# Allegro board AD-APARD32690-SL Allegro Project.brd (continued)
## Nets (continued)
GND: C2.1 C3.1 C5.2(N2) C7.1 C8.1 C10.1 C11.1 C12.1 C13.2(N2) C14.1 C15.1 C16.1 C17.1 C18.2(N2) C19.1 C20.2(N2) C21.2(N2) C22.2(N2) C23.1 C24.2(N2) C25.2(N2) C26.2(N2) C27.2(N2) C28.2(N2) C29.1 C30.1 C31.2(N2) C32.2(N2) C33.2(N2) C34.1 C35.2(N2) C36.2(N2) C37.1 C38.1 C39.2(N2) C40.2(N2) C41.1 C42.2(N2) C43.1 C44.2(N2) C45.2(N2) C46.2(N2) C47.2(N2) C48.1 C49.2(N2) C50.2(N2) C51.2(N2) C52.2(N2) C53.2(N2) C54.2(N2) C55.1 C56.2(N2) C57.1 C58.2(N2) C59.2(N2) C60.2(N2) C61.2(N2) C62.2(N2) C63.2(N2) C64.1 C65.1 C66.2(N2) C67.2(N2) C68.2(N2) C69.2(N2) C70.2(N2) C71.2(N2) C72.1 C73.2(N2) C74.2(N2) C75.2(N2) C76.2(N2) C77.1 C78.1 C79.2(N2) C80.2(N2) C81.2(N2) C82.2(N2) C83.2(N2) C84.2(N2) C85.2(N2) C86.2(N2) C87.2(N2) C88.2(N2) C89.2(N2) C90.2(N2) C91.2(N2) C92.1 C93.1 C94.2(N2) C95.1 C96.2(N2) C98.2(N2) C100.2(N2) C103.1 C107.1 C108.2(N2) C109.1 C110.1 C111.2(N2) C112.2(N2) C113.1 C114.2(N2) C115.1 C116.2(N2) C117.1 C118.2(N2) C119.2(N2) C120.2(N2) C121.1 C122.2(N2) C123.1 C124.1 C125.1 C126.1 C127.2(N2) C128.1 C129.2(N2) C130.2(N2) C131.1 D1.A(P) D2.2(N2) D6.A(P) D7.A(P) D9.2(N2) D10.A(P) D11.A(P) DS1.C JP1.3 M1.6 M1.12 M1.14 M1.26 M1.30 M1.37 M1.38 M1.39 M1.40 M1.41 M1.42 M1.43 M1.44 M1.45 M1.46 M1.47 M1.48 P2.6 P2.7 P5.4 P8.5 P8.11 P9.3 P9.5 P9.9 P10.A1 P10.A12 P10.B1 P10.B12 P13.5 P13.11 P14.1 P24.1(N1) P25.1(N1) P26.1(N1) P27.1(N1) P28.1(N1) P29.1(N1) P30.1(N1) P31.1(N1) Q1.2(S) Q2.2(S) Q3.2(S) R2.1 R4.2(N2) R6.1 R8.1 R9.1 R10.1 R12.1 R115.2(N2) R117.2(N2) R119.2(N2) R121.2(N2) R123.2(N2) R137.1 R145.2(N2) R147.1 R157.1 R158.1 R165.2(N2) R171.1 R175.1 S1.2(B) S3.2 S3.4(N4) U1.A8 U1.C11 U1.F1 U1.G11 U1.H11 U1.L11 U1.M8 U1.M11 U2.PAD U3.12 U3.20 U3.21 U4.PAD U5.4 U6.B3 U6.C1 U6.E5(VSSQ_2) U7.B3 U7.C1 U7.E5(VSSQ_2) U8.6 U8.PAD U9.9 U9.PAD U10.3 U10.4 U10.5 U10.8 Y1.2 Y1.4 Y2.2 Y2.4
GND_EARTH: C103.2(N2) C104.2(N2) C105.2(N2) C106.2(N2) P1.1 R147.2(N2)
GND_ISO: P11.1 P11.2
VDD_1P1_D: C25.1 C34.2(N2) C36.1 E3.2(N2) R124.1 U1.H12
VDD_3P3_D: C19.2(N2) C20.1 C21.1 C26.1 C27.1 C42.1 C66.1 C67.1 C69.1 C70.1 C71.1 C74.1 C75.1 C86.1 C89.1 C92.2(N2) C115.2(N2) C116.1 C117.2(N2) C118.1 C121.2(N2) C122.1 D5.1 D5.3 DS2.A(P) DS3.A(P) DS4.A(P) E1.2(N2) E5.1 E6.1 JP2.3 JP3.3 JP4.3 M1.9(VCC_IO) M1.10 P2.4 Q4.2(S) R120.1 R125.2(N2) R126.2(N2) R128.1 R132.1 R133.1 R136.1 R141.1 R142.1 R168.2(N2) S2.3 S2.4(N4) S4.1B(N6) S4.2B S4.3B U1.A4 U1.B11 U1.D1 U1.D12 U1.F11 U1.M3 U2.35 U8.12
VDD_5P0: C14.2(N2) C110.2(N2) C112.1 C126.2(N2) C127.1 JP3.1 JP4.1 P2.5 R13.2(N2) R14.2(N2) R15.2(N2) R16.2(N2) R17.1 R170.1 R173.2(N2) U3.4 U3.5 U3.6 U3.16(VIN234) U4.9 U4.10 U4.15 U4.16 U9.1 U9.2 U9.3 U9.4
VDD_5P0_INT: C1.2(N2) C8.2(N2) C11.2(N2) C13.1 JP1.1 L2.2(N2) R1.2(N2) U4.1 U4.2 U4.3
VDDA_BB: C29.2(N2) C31.1 U1.L10
VDDA_RF: C30.2(N2) C33.1 U1.M10
32KIN: C45.1 U1.K10 Y3.1
32KOUT: C53.1 U1.K11 Y3.2(N2)
ADC_IN0: P3.1 R89.2(N2)
ADC_IN1: P3.2 R110.2(N2)
ADC_IN2: P3.3 R90.2(N2)
ADC_IN3: P3.4 R111.2(N2)
ADC_IN4: P3.5 R91.2(N2)
ADC_IN5: P3.6 R112.2(N2)
ADC_IN6: P3.7 R92.2(N2)
ADC_IN7: P3.8(N8) R113.2(N2)
ADIN1100_TS_TIMER_MS_SEL: JP5.1 JP6.1
ADIN1110_INT: R56.1 R168.1 U2.25
ADIN1110_LINK_ST: R22.1 U2.4
ADIN1110_RESET: R55.1 U2.5
ADIN1110_SPI_CFG1: R166.1 U2.37
ADIN1110_TS_CAPT: R49.1 U2.40
ADIN1110_TS_TIMER_MS_SEL: R29.1 U2.30
BLE_LDO_1V1: C37.2(N2) C38.2(N2) C39.1 E4.2(N2) JP11.3
BLE_LDO_IN: C48.2(N2) C51.1 C129.1 JP11.2(COM) U1.K12
BOOT_LOAD_PDN_O: P39.1(N1) U1.J9
BT_ANT: C41.2(N2) L5.1 U1.L12
CAN0B_RX: P7.5 R84.2(N2)
CAN0B_TX: P7.6 R105.2(N2)
CAN1B_RX: P7.7 R85.2(N2)
CAN1B_TX: P7.8(N8) R106.2(N2)
FB1: C1.1 R1.1 R2.2(N2) R123.1 U3.7
FB2: C4.1 R5.1 R6.2(N2) U3.8
FB3: C6.1 R7.1 R8.2(N2) U3.9
FB4: C9.1 R11.1 R12.2(N2) U3.10
GPIO1_NINA: M1.1 P32.1(N1)
GPIO2_NINA: M1.2 P33.1(N1)
GPIO3_NINA: M1.3 P34.1(N1)
GPIO4_NINA: M1.4 P35.1(N1)
GPIO5_NINA: M1.5 P36.1(N1)
GPIO6_NINA: M1.7 P40.1(N1)
GPIO7_NINA: M1.8 P41.1(N1)
GPIO16_NINA: M1.16 P42.1(N1)
GPIO17_NINA: M1.17 P43.1(N1)
GPIO18_NINA: M1.18 P44.1(N1)
GPIO24_NINA: M1.24 P45.2(N2)
GPIO25_NINA: M1.25 P46.2(N2)
GPIO27_NINA: M1.27 P47.1(N1)
GPIO28_NINA: M1.28 P48.1(N1)
GPIO29_NINA: M1.29 P49.1(N1)
GPIO31_NINA: M1.31 P19.2(N2)
GPIO32_NINA: M1.32 P20.2(N2)
GPIO34_NINA: M1.34 P52.1(N1)
GPIO35_NINA: M1.35 P21.2(N2)
GPIO36_NINA: M1.36 P22.2(N2)
GPIO_1: P4.8(N8) R97.2(N2)
GPIO_2: P7.1 R77.2(N2)
GPIO_3: P7.2 R98.2(N2)
GPIO_4: P7.3 R78.2(N2)
GPIO_5: P7.4 R99.2(N2)
GPIO_6: P2.3 R83.2(N2)
GPIO_7: P8.7 R104.2(N2)
GPIO_8: P23.2(N2) R93.2(N2)
GPIO_9: P38.1(N1) R94.2(N2)
GPIO_10: C77.2(N2) R54.1 R133.2(N2) S3.1
GPIO_11: C78.2(N2) R31.1 R136.2(N2) S3.3
GPIO_I2C_1: P13.1 R160.1
GPIO_I2C_2: P13.2 R163.1
GPIO_I2C_3: P13.7 R161.1
GPIO_I2C_4: P13.8 R164.1
GPIO_USR_BTN: C57.2(N2) R71.1 R119.1 S2.1 S2.2
GPIO_USR_LED1: Q1.1 R74.2(N2) R115.1
GPIO_USR_LED2: Q2.1 R53.1 R117.1
GPIO_USR_LED3: Q3.1 R30.1 R121.1
HFXIN: C44.1 U1.L9 Y2.1
HFXOUT: C52.1 U1.M9 Y2.3(N2)
HYP_CLK_N: U1.A9 U6.B1 U7.B1
HYP_CLK_P: U1.A10 U6.B2 U7.B2
HYP_CS0_N: R38.1 U6.A3
HYP_CS1_N: R47.1 R176.1 U7.A3
HYP_D0: U1.C7 U6.D3 U7.D3
HYP_D1: U1.C8 U6.D2 U7.D2
HYP_D2: U1.C9 U6.C4 U7.C4
HYP_D3: U1.C10 U6.D4 U7.D4
HYP_D4: U1.B7 U6.D5 U7.D5
HYP_D5: U1.B8 U6.E3 U7.E3
HYP_D6: U1.B9 U6.E2 U7.E2
HYP_D7: U1.B10 U6.E1 U7.E1
HYP_RSTN: R18.1 U6.A4 U7.A4
HYP_RWDS: R65.1 U6.C3 U7.C3
I2C0A_SCL: P13.3 P13.9 R32.1 R142.2(N2)
I2C0A_SDA: P13.4 P13.10 R57.1 R141.2(N2)
I2C1A_SCL: P5.1 R103.2(N2) R144.1
I2C1A_SDA: P5.2 R82.2(N2) R143.1
IO_REF_ARD: C107.2(N2) C108.1 JP2.2(COM) P2.2 R143.2(N2) R144.2(N2)
LT8692S_1P1: C7.2(N2) C9.2(N2) C17.2(N2) C100.1 E3.1 L1.2(N2) R11.2(N2)
LT8692S_1P8: C6.2(N2) C10.2(N2) C16.2(N2) C98.1 E2.1 L4.2(N2) R7.2(N2)
LT8692S_3P3: C4.2(N2) C12.2(N2) C95.2(N2) C96.1 E1.1 L3.2(N2) R5.2(N2)
LT8692S_PG: DS1.A(P) R17.2(N2) U3.19
MCU_RESET_N: C55.2(N2) P9.10(N5) R120.2(N2) S1.1 U1.K9
OWM_IO: P6.4 P18.1 R21.1 R126.1
OWM_PE: P6.3 Q4.1 R48.1 R132.2(N2)
PI+: C106.1 D8.1 P1.3(N3) P16.1 P16.2(N2) R155.2(N2)
PI-: C104.1 D8.2(N2) P1.2 P17.1 P17.2(N2) R156.2(N2)
QSPI_SCK: U1.J1 U5.6
QSPI_SDIO0: U1.J2 U5.5
QSPI_SDIO1: U1.H2 U5.2
QSPI_SDIO2: U1.J3 U5.3(WP_N/SIO2)
QSPI_SDIO3: U1.H3 U5.7
QSPI_SS0: U1.H1 U5.1
RESET_NINA: M1.19 R114.2(N2)
RXN: R135.1 R146.1 U2.13
RXP: R129.1 R140.1 U2.14
SHIELD: C123.2(N2) P10.GND1 P10.GND2 P10.GND3(N9) P10.GND4 R145.1
SPI0_MISO: P4.3 P22.1 R107.2(N2)
SPI0_MOSI: P4.4 P21.1 R87.2(N2)
SPI0_SCK: P4.2 P19.1 R108.2(N2)
SPI0_SDIO2: P4.6 P46.1 R88.2(N2)
SPI0_SDIO3: P4.7 P45.1 R109.2(N2)
SPI0_SS1: P4.1 R86.2(N2)
SPI1A_MISO: P5.6 R45.1
SPI1A_MOSI: P5.7 R72.1
SPI1A_SCLK: P5.5 R44.1
SPI1A_SDIO2: P5.9(N9) R46.1
SPI1A_SDIO3: P5.10 R73.1
SPI1A_SS0: P5.8 R69.1
SPI1A_SS1: P6.1 R70.1
SPI1A_SS2: P6.2 R43.1
SPI2_MISO_MAXQ1065: R75.2(N2) U8.4
SPI2_MOSI_MAXQ1065: R96.2(N2) U8.3
SPI2_SCK_MAXQ1065: R95.2(N2) U8.2
SPI2A_SS0_MAXQ1065: R76.2(N2) U8.5
SPI3A_MISO_ADIN1110: R167.1 U1.C3 U2.2
SPI3A_MOSI_ADIN1110: U1.B2 U2.1
SPI3A_SCLK_ADIN1110: U1.B3 U2.38
SPI3A_SS0_ADIN1110: R24.1 U2.29
SPI4A_MISO: JP8.3 R59.1
SPI4A_MOSI: JP7.3 R33.1
SPI4A_SCLK: JP10.3 R34.1
SPI4A_SDIO2: JP6.3 R60.1
SPI4A_SDIO3: P8.10 R35.1
SPI4A_SS0: JP9.3 R58.1
SPI4A_SS1: JP5.3 R61.1
SWPD_EN: R138.1 U2.33
TCK: P9.4 R159.1
TDO: P4.5 P20.1 R20.1
TMS: P9.2 R162.1
TRX_N: C99.1 D9.1 P15.1(N1) R134.2(N2) R146.2(N2) R151.1 T1.2
TRX_P: C97.2(N2) D2.1 P12.1(N1) R131.2(N2) R140.2(N2) R148.1 T1.1
TXN: R129.2(N2) R134.1 U2.12
TXP: R131.1 R135.2(N2) U2.15
UART0_RX: P9.8 R79.2(N2)
UART0_TX: P9.6 R100.2(N2)
UART1A_CTS: JP10.1 P6.6 R80.2(N2)
UART1A_RTS: JP9.1 P6.5 R81.2(N2)
UART1A_RX: JP8.1 P6.7 R101.2(N2)
UART1A_TX: JP7.1 P6.8(N8) R102.2(N2)
UART2A_CTS: M1.20 R36.1
UART2A_RTS: M1.21 R62.1
UART2A_RX: M1.22 R37.1
UART2A_TX: M1.23 R63.1
UNNAMED_2_ADLT3040_I358_FAULTN: R170.2(N2) U9.5
UNNAMED_2_ADLT3040_I358_FS: C124.2(N2) R169.1 R174.2(N2) R175.2(N2) U9.7
UNNAMED_2_ADLT3040_I358_ILIM: R171.2(N2) U9.6
UNNAMED_2_ADLT3040_I358_OUT1: C128.2(N2) JP11.1 U9.10 U9.11 U9.12
UNNAMED_2_ADLT3040_I358_VIN: C125.2(N2) R169.2(N2) U9.8(VIN)
UNNAMED_2_ADLT8692S_I193_EN: C2.2(N2) C3.2(N2) C15.2(N2) D1.C D4.C F3.2(N2) R3.2(N2) U3.1 U3.2
UNNAMED_2_ADLT8692S_I193_EN1: R3.1 R4.1 U3.3
UNNAMED_2_ADLT8692S_I193_INTVCC: C5.1 U3.11
UNNAMED_2_ADLT8692S_I193_SW1: L2.1 U3.17
UNNAMED_2_ADLT8692S_I193_SW2: L3.1 U3.15
UNNAMED_2_ADLT8692S_I193_SW3: L4.1 U3.14
UNNAMED_2_ADLT8692S_I193_SW4: L1.1 U3.13
UNNAMED_2_CAP_I379_N1: C130.1 D11.C R172.1 R173.1 U10.1 U10.2
UNNAMED_2_CAP_I385_N2: C131.2(N2) P37.1 R174.1 U10.6(VOUT_S) U10.7
UNNAMED_2_DIO_I282_N: D3.C D4.A(P)
UNNAMED_2_FERRITE_I316_N1: E4.1 R124.2(N2)
UNNAMED_2_LINLTC4415_I130_CLIM1: R9.2(N2) U4.4
UNNAMED_2_LINLTC4415_I130_CLIM2: R10.2(N2) U4.5
UNNAMED_2_LINLTC4415_I130_EN2N: JP1.2(COM) U4.6
UNNAMED_2_LINLTC4415_I130_STAT1N: R15.1 U4.14
UNNAMED_2_LINLTC4415_I130_STAT2N: R16.1 U4.11
UNNAMED_2_LINLTC4415_I130_WARN1N: R14.1 U4.13
UNNAMED_2_LINLTC4415_I130_WARN2N: R13.1 U4.12(WARN2_N)
UNNAMED_2_NC2P_I395_N2: P37.2(N2) R172.2(N2)
UNNAMED_3_ADMAX32690_I367_P0_6: R48.2(N2) U1.G2
UNNAMED_3_ADMAX32690_I367_P0_7: R53.2(N2) U1.F2
UNNAMED_3_ADMAX32690_I367_P0_9: R21.2(N2) U1.G1
UNNAMED_3_ADMAX32690_I367_P0_10: R30.2(N2) U1.F3
UNNAMED_3_ADMAX32690_I367_P0_11: R31.2(N2) U1.C1
UNNAMED_3_ADMAX32690_I367_P0_13: R24.2(N2) U1.A3
UNNAMED_3_ADMAX32690_I367_P0_14: R18.2(N2) U1.C6
UNNAMED_3_ADMAX32690_I367_P0_16: R56.2(N2) U1.D3
UNNAMED_3_ADMAX32690_I367_P0_17: R55.2(N2) U1.C2
UNNAMED_3_ADMAX32690_I367_P0_18: R57.2(N2) U1.G6
UNNAMED_3_ADMAX32690_I367_P0_19: R54.2(N2) U1.D2
UNNAMED_3_ADMAX32690_I367_P0_20: R32.2(N2) U1.F6
UNNAMED_3_ADMAX32690_I367_P0_21: R22.2(N2) U1.F4
UNNAMED_3_ADMAX32690_I367_P0_22: R29.2(N2) U1.F7
UNNAMED_3_ADMAX32690_I367_P0_23: R49.2(N2) U1.G7
UNNAMED_3_ADMAX32690_I367_P0_24: R159.2(N2) U1.H8
UNNAMED_3_ADMAX32690_I367_P0_25: R162.2(N2) U1.J8
UNNAMED_3_ADMAX32690_I367_P0_26: R160.2(N2) U1.G4
UNNAMED_3_ADMAX32690_I367_P0_27: R163.2(N2) U1.H4
UNNAMED_3_ADMAX32690_I367_P0_28: R161.2(N2) U1.F5
UNNAMED_3_ADMAX32690_I367_P0_29: R164.2(N2) U1.G5
UNNAMED_3_ADMAX32690_I367_P0_30: R20.2(N2) U1.K1
UNNAMED_3_ADMAX32690_I367_P1: R58.2(N2) U1.E5
UNNAMED_3_ADMAX32690_I367_P1_1: R59.2(N2) U1.D5
UNNAMED_3_ADMAX32690_I367_P1_2: R60.2(N2) U1.B4
UNNAMED_3_ADMAX32690_I367_P1_3: R63.2(N2) U1.E4
UNNAMED_3_ADMAX32690_I367_P1_4: R61.2(N2) U1.B5
UNNAMED_3_ADMAX32690_I367_P1_5: R62.2(N2) U1.A2
UNNAMED_3_ADMAX32690_I367_P1_7: R65.2(N2) U1.A11
UNNAMED_3_ADMAX32690_I367_P1_9: R34.2(N2) U1.C5
UNNAMED_3_ADMAX32690_I367_P1_10: R33.2(N2) U1.C4
UNNAMED_3_ADMAX32690_I367_P1_11: R35.2(N2) U1.A5
UNNAMED_3_ADMAX32690_I367_P1_12: R36.2(N2) U1.D4
UNNAMED_3_ADMAX32690_I367_P1_15: R38.2(N2) U1.B6
UNNAMED_3_ADMAX32690_I367_P1_16: R37.2(N2) U1.B1
UNNAMED_3_ADMAX32690_I367_P1_19: R69.2(N2) U1.K8
UNNAMED_3_ADMAX32690_I367_P1_20: R71.2(N2) U1.K7
UNNAMED_3_ADMAX32690_I367_P1_21: R70.2(N2) U1.H7
UNNAMED_3_ADMAX32690_I367_P1_22: R72.2(N2) U1.M7
UNNAMED_3_ADMAX32690_I367_P1_23: R73.2(N2) U1.F8
UNNAMED_3_ADMAX32690_I367_P1_24: R44.2(N2) U1.L8
UNNAMED_3_ADMAX32690_I367_P1_25: R43.2(N2) U1.J7
UNNAMED_3_ADMAX32690_I367_P1_28: R45.2(N2) U1.L7
UNNAMED_3_ADMAX32690_I367_P1_29: R46.2(N2) U1.G8
UNNAMED_3_ADMAX32690_I367_P1_30: R47.2(N2) U1.A7
UNNAMED_3_ADMAX32690_I367_P2: R101.1 U1.D6
UNNAMED_3_ADMAX32690_I367_P2_1: R81.1 U1.D7
UNNAMED_3_ADMAX32690_I367_P2_2: R104.1 U1.D9
UNNAMED_3_ADMAX32690_I367_P2_3: R82.1 U1.E2
UNNAMED_3_ADMAX32690_I367_P2_4: R103.1 U1.E3
UNNAMED_3_ADMAX32690_I367_P2_5: R80.1 U1.E6
UNNAMED_3_ADMAX32690_I367_P2_6: R102.1 U1.E7
UNNAMED_3_ADMAX32690_I367_P2_7: R83.1 U1.E9
UNNAMED_3_ADMAX32690_I367_P2_8: R105.1 U1.F9
UNNAMED_3_ADMAX32690_I367_P2_9: R106.1 U1.G3
UNNAMED_3_ADMAX32690_I367_P2_10: R84.1 U1.G9
UNNAMED_3_ADMAX32690_I367_P2_11: R77.1 U1.H5
UNNAMED_3_ADMAX32690_I367_P2_12: R74.1 U1.H6
UNNAMED_3_ADMAX32690_I367_P2_13: R98.1 U1.J4
UNNAMED_3_ADMAX32690_I367_P2_14: R79.1 U1.K5
UNNAMED_3_ADMAX32690_I367_P2_15: R76.1 U1.J6
UNNAMED_3_ADMAX32690_I367_P2_16: R109.1 U1.K2
UNNAMED_3_ADMAX32690_I367_P2_17: R108.1 U1.K3
UNNAMED_3_ADMAX32690_I367_P2_18: R97.1 U1.K4
UNNAMED_3_ADMAX32690_I367_P2_19: R100.1 U1.J5
UNNAMED_3_ADMAX32690_I367_P2_20: R96.1 U1.K6
UNNAMED_3_ADMAX32690_I367_P2_21: R87.1 U1.L1
UNNAMED_3_ADMAX32690_I367_P2_22: R107.1 U1.L2
UNNAMED_3_ADMAX32690_I367_P2_23: R88.1 U1.L3
UNNAMED_3_ADMAX32690_I367_P2_24: R85.1 U1.L4
UNNAMED_3_ADMAX32690_I367_P2_25: R99.1 U1.L5
UNNAMED_3_ADMAX32690_I367_P2_26: R75.1 U1.L6
UNNAMED_3_ADMAX32690_I367_P2_27: R86.1 U1.M2
UNNAMED_3_ADMAX32690_I367_P2_28: R78.1 U1.M5
UNNAMED_3_ADMAX32690_I367_P2_29: R95.1 U1.M6
UNNAMED_3_ADMAX32690_I367_P3: R114.1 U1.D8
UNNAMED_3_ADMAX32690_I367_P3_1: R93.1 U1.E8
UNNAMED_3_ADMAX32690_I367_P3_2: R89.1 U1.E10
UNNAMED_3_ADMAX32690_I367_P3_3: R110.1 U1.E11
UNNAMED_3_ADMAX32690_I367_P3_4: R90.1 U1.E12
UNNAMED_3_ADMAX32690_I367_P3_5: R111.1 U1.F10
UNNAMED_3_ADMAX32690_I367_P3_6: R92.1 U1.F12
UNNAMED_3_ADMAX32690_I367_P3_7: R91.1 U1.G10
UNNAMED_3_ADMAX32690_I367_P3_8: R112.1 U1.H10
UNNAMED_3_ADMAX32690_I367_P3_9: R113.1 U1.J10
UNNAMED_3_ADMAX32690_I367_P4: R94.1 U1.H9
UNNAMED_3_ADMAX32690_I367_VREG1: C18.1 U1.J12
UNNAMED_3_ANT4PV3_I701_FEED: ANT1.4 C43.2(N2) L5.2(N2)
UNNAMED_3_DIOLED4PV5_I542_C1: D5.2 R122.2(N2)
UNNAMED_3_DIOLED4PV5_I542_C2: D5.4(C2) R118.2(N2)
UNNAMED_3_DIOLED_I538_N: DS2.C R116.2(N2)
UNNAMED_3_NC2P_I646_N2: P18.2(N2) R127.2(N2)
UNNAMED_3_RES_I645_N1: Q4.3 R127.1
UNNAMED_3_RES_I698_N1: Q1.3 R116.1
UNNAMED_3_RES_I699_N1: Q2.3 R118.1
UNNAMED_3_RES_I700_N1: Q3.3 R122.1
UNNAMED_7_ADIN1110V2_I781_AVDDH1: C64.2(N2) C90.1 E6.2(N2) U2.16 U2.17
UNNAMED_7_ADIN1110V2_I781_AVDDL: C65.2(N2) C88.1 E5.2(N2) U2.22
UNNAMED_7_ADIN1110V2_I781_CEXT2: C72.2(N2) U2.19
UNNAMED_7_ADIN1110V2_I781_CEXT3: C73.1 U2.20
UNNAMED_7_ADIN1110V2_I781_DLDO1P1: C68.1 C93.2(N2) U2.23 U2.24
UNNAMED_7_ADIN1110V2_I781_LED0: R139.2(N2) U2.3
UNNAMED_7_ADIN1110V2_I781_LED1: R128.2(N2) R130.2(N2) U2.6
UNNAMED_7_ADIN1110V2_I781_TEST1: R125.1 U2.26
UNNAMED_7_ADIN1110V2_I781_TX2P4ENN: R137.2(N2) U2.31
UNNAMED_7_CAP_I819_N1: C102.1 R150.1 R151.2(N2) T1.7(SEC_2)
UNNAMED_7_CAP_I819_N2: C102.2(N2) L6.3 P54.1(N1) R150.2(N2) R154.1
UNNAMED_7_CAP_I823_N1: C101.1 R148.2(N2) R149.1 T1.6
UNNAMED_7_CAP_I823_N2: C101.2(N2) L6.4(N4) P53.1(N1) R149.2(N2) R153.1
UNNAMED_7_CAP_I855_N1: C105.1 R152.2(N2)
UNNAMED_7_CAP_I861_N1: C94.1 C97.1 C99.2(N2) T1.5
UNNAMED_7_CHOKE4PV5_I912_N1: L6.1 R153.2(N2) R155.1
UNNAMED_7_CHOKE4PV5_I912_N2: L6.2 R154.2(N2) R156.1
UNNAMED_7_DIOLED_I752_N: DS3.C R139.1
UNNAMED_7_DIOLED_I761_N: DS4.C R130.1
UNNAMED_7_RES_I857_N1: R152.1 T1.3 T1.4
UNNAMED_7_RES_I906_N2: R166.2(N2) S4.3A
UNNAMED_7_RES_I907_N2: R167.2(N2) S4.2A
UNNAMED_7_RES_I909_N2: R138.2(N2) S4.1A
UNNAMED_9_ADMAXQ1065_I325_CEXT: C91.1 U8.1
UNNAMED_9_ADMAXQ1065_I325_PDWN: P23.1 R165.1 U8.7
UNNAMED_9_CAP_I264_N1: C109.2(N2) C111.1 JP3.2(COM) P13.6 P13.12(VCC2)
UNNAMED_9_CAP_I265_N1: C113.2(N2) C114.1 JP4.2(COM) P8.6 P8.12(VCC2)
UNNAMED_9_CN12PV3_I138_P1: JP9.2(COM) P8.1
UNNAMED_9_CN12PV3_I138_P2: JP7.2(COM) P8.2
UNNAMED_9_CN12PV3_I138_P3: JP8.2(COM) P8.3
UNNAMED_9_CN12PV3_I138_P4: JP10.2(COM) P8.4
UNNAMED_9_CN12PV3_I138_P8: JP5.2(COM) P8.8
UNNAMED_9_CN12PV3_I138_P9: JP6.2(COM) P8.9
UNNAMED_9_CN16PAB4GND_I308_N3: P10.B5 R158.2(N2)
UNNAMED_9_CN16PAB4GND_I314_N3: P10.A5 R157.2(N2)
USB_DN: L7.1 U1.C12
USB_DN_CM: D6.C L7.2 P10.A7 P10.B7
USB_DP: L7.4(N4) U1.B12
USB_DP_CM: D7.C L7.3 P10.A6 P10.B6
VPWR_IN: F3.1 P2.8(N8) P14.2(N2)
VPWR_USB: C120.1 D3.A(P) D10.C P10.A4 P10.A9 P10.B4 P10.B9 U4.7 U4.8
VREF_ADC: C22.1 P5.3 U1.G12
VUSB0P9: C35.1 U1.D11(VUSB0P9)
XTAL_I: C62.1 U2.8 Y1.1
XTAL_O: C63.1 U2.9(XTAL_O) Y1.3(N2)

Pads without a net: ANT1 1 2 3; M1 11 13 15 33; P2 1; P9 7; P10 A8 B8; P11 3; U2 7 10 11 18 21 27 28 32 34 36 39; U3 18; U6 A2 A5 B5 C2 C5; U7 A2 A5 B5 C2 C5; U8 8 9 10 11

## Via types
v1: diameter 0.356, hole 0.203, TOP to BOTTOM, 477 vias
v2: diameter 0.203, hole 0.102, TOP to L2_GND, 547 vias
v3: diameter 0.203, hole 0.102, L2_GND to L3_SIG, 88 vias
v4: diameter 0.203, hole 0.102, L3_SIG to L4_GND, 33 vias
v5: diameter 0.203, hole 0.102, L4_GND to L5_PWR, 12 vias
v6: diameter 0.508, hole 0.254, TOP to BOTTOM, 551 vias

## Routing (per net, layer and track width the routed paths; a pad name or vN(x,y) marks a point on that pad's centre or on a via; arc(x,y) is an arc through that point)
1V8_D: length 100.9
  TOP w0.127: U1.A6 98.73,28.4 98.23,27.91 ; 100.95,25.04 U1.E1
  TOP w0.152: U1.M4 103.87,27.7 104.33,27.24 104.33,26.73 105.03,26.04 v1(105.28,26.04)
  TOP w0.254: 101.12,24.86 100.95,25.04
  TOP w0.305: v1(81.51,27.48) 81.51,28.08 C85.1 81.63,29.08 81.34,29.37 C87.1 81.22,29.37 81.17,29.41 C59.1 ; v1(78.77,32.67) 78.77,33.24 79.06,33.53 C81.1
  TOP w0.381: v1(77.76,27.48) 77.07,27.48 C84.1 77,27.5 C54.1 ; 98.23,27.91 97.53,27.21 C58.1 ; v1(77.77,36.43) 77.75,36.45 77.12,36.45 C82.1 77,36.52 C49.1 ; 81.52,37.35 v1(81.52,36.43) ; 81.52,37.35 C80.1 C79.1 ; 81.52,37.35 81.51,37.35 C46.1 ; v1(78.76,23.72) 78.76,23 C83.1 ; v1(101.09,22.67) 101.09,23.26 C28.1 101.12,23.29 C56.1 101.12,24.86 ; R176.2 v1(84.71,22.99)
  TOP w0.508: C58.1 96.03,27.21 C23.2 v1(95.44,27.19) 95.42,27.21 C32.1 ; v6(127,24.38) C119.1 124.49,25.05 P9.1 ; JP2.1 v6(42.53,7) ; C40.1 101.2,13.52 C76.1 99.92,13.49 U5.8
  L2_GND w0.127: 102.23,31.43 102.23,30.54 102.35,30.43 v2(102.35,30.15)
  L2_GND w0.152: v1(102.74,31.94) 102.23,31.43
  L3_SIG w0.089: v1(98.01,31.78) 99,31.78 100.6,30.18 v3(100.6,29.8)
  L6_PWR w0.508: v1(95.44,27.19) 95.44,27.88
  L6_PWR w0.889: v6(40.58,8.38) v6(41.27,8.38) v6(41.97,8.38) 42.53,7.82 v6(42.53,7) 42.53,5.6 43.43,4.7 69.6,4.7 73.85,8.95 73.85,20.83 75.5,22.48
  BOTTOM w0.127: U6.E4 v1(77.77,36.43) ; U7.B4 v1(81.51,27.48) ; U7.D1 v1(78.76,23.72) ; U6.D1 v1(78.77,32.67) ; U6.B4 v1(81.52,36.43) ; U7.E4 v1(77.76,27.48)
  BOTTOM w0.381: v1(105.28,26.04) 105.79,26.55 C61.1 C47.1 ; v1(102.74,31.94) 103.22,31.94 C60.1 ; v1(98.01,31.78) 98.33,31.46 C50.1
  BOTTOM w0.508: C24.1 103.47,30.56 C60.1
  vias: v6(100.58,12.79) v6(101.22,12.79)
GND: length 964.4
  TOP w0.127: v2(101.59,25.52) 101.3,25.81 U1.F1 ; v2(105,29.53) 103.95,29.53 103.52,29.1 U1.M8 ; U1.A8 v2(98.49,29.1)
  TOP w0.152: U1.L11 U1.M11 arc(103.98,30.27) 104.47,30.59
  TOP w0.254: U3.20 28.71,15.1 v6(29.08,14.73) ; U8.6 v1(105.56,17.46) ; v6(29.84,12.95) 29.98,13.09 U3.12
  TOP w0.381: C123.1 11.1,32.14 ; C123.1 11.65,31.56 ; C123.1 11.1,30.98 ; C112.2 54.64,5.78 ; C112.2 54.64,4.76 ; C112.2 55.18,5.27 ; 90.83,9.12 U5.4 ; U5.4 90.83,10.24 ; U5.4 91.88,9.68 ; U5.4 v1(89.53,9.68) ; R158.1 3.82,20.94 ; R158.1 3.82,19.7 ; R158.1 3.25,20.32 ; 125.17,7.53 Q1.2 ; Q1.2 125.93,8.48 ; Q1.2 125.17,9.77 v1(124.78,10.16) ; Q1.2 124.41,8.48 ; C109.1 142.44,39.62 ; C109.1 141.27,39.62 ; C109.1 v6(141.86,40.26) ; 118.44,9.54 R117.2 ; R117.2 117.86,10.16 ; R117.2 118.18,10.41 v1(117.79,10.41) ; P8.5 146.48,4.57 ; P8.5 144.09,4.57 ; P8.5 145.29,3.38 ; 147.83,39.95 P13.11 ; P13.11 147.83,42.34 ; P13.11 146.63,41.15 ; P13.11 149.02,41.15 ; 66.99,7.98 D11.A ; D11.A 67.86,8.69 ; D11.A 66.99,9.4 ; D11.A 66.13,8.69 ; C129.2 56.32,22.7 ; C129.2 55.31,22.7 ; C129.2 55.82,23.24 ; C110.1 55.21,6.54 ; C110.1 54.67,7.12 ; C110.1 54.67,5.96 ; 11.1,27.89 R157.1 11.1,29.13 ; v6(58.48,18.73) 58.32,18.57 C125.1 58.32,17.88 58.49,17.71 U9.9 58.49,14.74 U9.PAD ; 3.44,6.1 P14.1 ; P14.1 4.83,4.71 ; P14.1 4.83,7.48 ; P14.1 6.21,6.1 ; C128.1 55.63,18.68 ; C128.1 55.63,17.51 ; C128.1 55.09,18.1 ; P30.1 136.55,1.91 ; P30.1 134.09,1.91 ; P30.1 135.32,3.14 ; v1(110.74,32.35) C55.1 ; P28.1 13.53,32.79 ; P28.1 14.76,31.56 ; P28.1 12.29,31.56 ; P28.1 13.53,30.33 ; S3.2 131.32,2.75 ; S3.2 v1(131.32,0.76) ; S3.2 131.95,1.88 ; 143.7,17.82 P29.1 ; P29.1 142.47,19.05 ; P29.1 144.93,19.05 ; v6(149.73,18.41) C117.1 v6(149.03,17.72) ; 64.86,12.05 U10.5 ; U10.5 65.29,12.97 ; U10.5 64.86,13.88 ; 62.91,12.05 U10.8 ; U10.8 62.91,13.88 ; U10.8 62.47,12.97 ; 29.06,50.8 P31.1 ; P31.1 30.29,49.57 ; P31.1 30.29,52.03 ; P31.1 31.52,50.8 ; v6(145.87,17.72) C115.1 v6(145.1,18.41) ; 61.85,44.99 C42.2 ; C42.2 62.36,44.45 ; C42.2 62.87,44.99 ; 41.91,49.54 P5.4 ; P5.4 43.17,50.8 ; P5.4 41.91,52.06 ; P5.4 40.65,50.8 ; v6(142.11,3.68) C113.1 ; C113.1 141.53,2.98 ; C113.1 142.7,2.98 ; D10.A 13.13,25.08 ; D10.A 12.47,25.64 ; D10.A 12.47,24.52 ; D10.A 11.81,25.08 ; 122.81,30.1 P9.9 124.46,30.72 ; S1.2 115.21,34.02 ; S1.2 114.11,33.37 ; S1.2 113,34.02 ; S1.2 114.11,34.66 ; 135.42,42.42 P25.1 ; P25.1 136.65,41.19 ; P25.1 136.65,43.65 ; P25.1 137.88,42.42 ; 47.05,5.96 C107.1 47.05,7.12 ; 51,18.61 JP1.3 51.56,19.62 ; C118.2 v6(149.73,19.56) ; C118.2 149.03,19.58 C89.2 ; C118.2 149.01,19.05 ; C118.2 149.01,20.07 ; 61.33,17.51 C124.1 ; C124.1 61.88,18.1 ; C124.1 61.33,18.68 ; Q3.2 122.12,8.48 ; Q3.2 121.36,7.53 ; Q3.2 121.36,9.77 v1(120.97,10.16) ; Q3.2 120.6,8.48 ; C76.2 99.95,15.01 ; C76.2 100.46,14.47 ; C76.2 99.44,14.47 ; v1(99.31,35.56) v1(99.31,35.05) 99.31,34.55 C27.2 99.31,34.54 99.31,33.43 C70.2 ; D2.2 53.88,39.84 ; D2.2 53.37,39.15 ; D2.2 53.37,40.61 v1(53.34,40.64) ; D2.2 52.86,39.84 ; P13.5 146.48,41.15 ; P13.5 144.09,41.15 ; P13.5 145.29,39.95 ; P13.5 145.29,42.34 ; C114.2 143.83,2.96 ; C114.2 142.81,2.96 ; C114.2 v6(143.32,3.68) ; v1(79.76,23.72) 79.76,22.95 C83.2 ; 132.92,10.6 C77.1 132.33,11.14 ; R115.2 v1(125.41,10.16) ; U10.4 65.29,8.37 ; U10.4 64.86,7.45 ; U10.4 64.86,9.28 ; 65.75,14.61 C131.1 65.21,14.02 ; P2.6 57.07,1.6 ; P2.6 57.07,3.48 ; P2.6 55.19,3.48 ; P2.6 55.19,1.6 ; 147.93,34.29 P27.1 ; P27.1 150.39,34.29 ; P27.1 149.16,33.06 ; P27.1 149.16,35.52 ; R121.2 v1(121.6,10.16) ; 55.59,10.22 C127.2 ; C127.2 55.06,10.73 ; C127.2 55.59,11.24 ; C116.2 145.87,19.58 C86.2 ; C116.2 145.89,20.07 ; C116.2 145.89,19.05 ; C116.2 v6(145.1,19.56) ; 122.81,27.56 P9.5 124.46,26.94 ; 12.7,0.89 P26.1 ; P26.1 12.7,4.06 ; P26.1 14.29,2.48 ; P26.1 11.11,2.48 ; 26.9,1.27 DS1.C ; DS1.C 26.9,2.54 ; DS1.C 27.55,1.91 ; DS1.C 26.26,1.91 ; v1(77.76,28.48) 77.03,28.48 C84.2 75.9,28.48 C54.2 ; 63.63,39.75 R137.1 64.21,40.37 ; v1(53.34,32.13) 53.37,32.16 D9.2 ; v1(75.88,38.04) C49.2 76.03,37.37 76.96,37.37 77.03,37.44 C82.2 77.1,37.43 v1(77.77,37.43) ; 57.73,1.6 P2.7 ; P2.7 59.61,1.6 ; P2.7 57.73,3.48 ; P2.7 59.61,3.48 ; 2.1,15.85 P24.1 ; P24.1 2.1,18.31 ; P24.1 0.86,17.08 ; P24.1 3.33,17.08 ; P8.11 149.02,4.57 ; P8.11 147.83,3.38 ; P8.11 147.83,5.77 ; P8.11 146.63,4.57 ; v1(116.2,18.67) C57.1 ; C130.2 65.02,6.6 ; C130.2 64.49,6.1 ; C130.2 64.49,7.11 ; 60.63,9.91 R171.1 60.01,9.34 ; Q2.2 118.31,8.48 ; Q2.2 116.79,8.48 ; Q2.2 117.55,7.53 ; Q2.2 117.55,9.77 117.28,10.03 v1(117.28,10.41) ; 124.46,26.91 P9.3 122.81,26.29 ; C83.2 80.32,22.92 ; C83.2 79.79,23.43 ; C83.2 79.79,22.42 ; D9.2 53.37,33.63 ; D9.2 53.88,32.93 ; D9.2 52.86,32.93 ; C111.2 143.57,39.6 ; C111.2 142.56,39.6 ; C111.2 v6(143.07,40.26) ; 116.28,17.59 R119.2 116.85,16.97 ; 55.02,9.53 C126.1 ; C126.1 55.57,10.11 ; C126.1 55.57,8.94 ; 27.24,6.16 C100.2 27.78,5.65 ; S3.4 v1(130.05,0.76) ; S3.4 130.05,2.75 ; S3.4 129.41,1.88 ; 128.45,10.6 C78.1 129.03,11.14 ; R165.2 104.95,14.53 ; R165.2 103.71,14.53 ; R165.2 104.33,15.11 ; v1(104.9,32.83) C51.2 ; C108.2 47.02,5.78 ; C108.2 47.56,5.27 ; C108.2 47.02,4.76 ; 26.15,12.18 R2.1 24.9,12.18 ; 24.75,12.18 R123.2 23.51,12.18 ; 64.21,7.45 U10.3 64.21,9.28 ; C48.1 v1(104.9,33.97) ; v6(101.22,15.17) C40.2 ; C5.2 31.76,9.15 ; C5.2 30.59,9.15 ; C5.2 v6(31.18,7.94) ; C119.2 127,26.54 ; C119.2 126.49,26.01 ; C119.2 127.51,26.01 ; 58.75,20.45 R175.1 59.32,21.07
  TOP w0.508: P9.5 v6(126.3,27.56) ; v6(24.13,7.18) R8.1 ; v6(26.54,5.59) C16.1 ; R157.1 v6(11.81,28.51) ; 96.36,32.62 C21.2 ; 96.36,32.62 C67.2 ; 96.36,32.62 v6(96.36,33.3) ; P10.B12 P10.A1 ; P9.3 v6(126.3,26.29) ; C17.1 27.76,6.18 C100.2 27.75,6.13 v6(27.75,5.59) ; v6(27.75,7.94) 27.75,8.58 R12.1 ; C92.1 64.08,38.8 v6(63.44,38.8) ; v6(60.64,36.89) C90.2 ; v6(20.57,5.59) C95.1 ; R9.1 v1(48.01,20.7) ; v6(25.46,5.59) C98.2 ; R10.1 v1(46.86,20.7) ; v6(24.13,12.83) R123.2 ; v6(21.65,5.59) C96.2 ; JP1.3 v1(51,20.7) ; P10.B1 P10.A12 ; C107.1 v6(47.62,6.54) ; v6(25.53,12.83) R2.1 ; v6(60.64,37.91) C64.1 ; v6(22.73,7.94) R6.1 ; C69.2 64.21,37.28 63.82,36.89 v6(63.44,36.89) ; P9.9 v6(126.3,30.1)
  TOP w0.635: R145.2 v6(4.83,33.66)
  L2_GND w0.127: 100.08,30.69 100.08,30.42 100.25,30.24 v2(100.25,30.15)
  L2_GND w0.381: P27.1 149.16,35.52 ; P27.1 149.16,33.06 ; P27.1 147.93,34.29 ; P27.1 150.39,34.29 ; 144.09,4.57 P8.5 ; P8.5 145.29,3.38 ; P8.5 145.29,5.77 ; P8.5 146.48,4.57 ; P25.1 137.88,42.42 ; P25.1 136.65,43.65 ; P25.1 136.65,41.19 ; P25.1 135.42,42.42 ; P30.1 135.32,3.14 ; P30.1 136.55,1.91 ; P30.1 134.09,1.91 ; 0.86,17.08 P24.1 ; P24.1 2.1,18.31 ; P24.1 2.1,15.85 ; P24.1 3.33,17.08 ; P14.1 6.21,6.1 ; P14.1 4.83,7.48 ; P14.1 4.83,4.71 ; P14.1 3.44,6.1 ; 143.7,17.82 P29.1 ; P29.1 142.47,19.05 ; P29.1 144.93,19.05 ; P29.1 143.7,20.28 ; 146.63,41.15 P13.11 ; P13.11 149.02,41.15 ; P13.11 147.83,39.95 ; P13.11 147.83,42.34 ; 55.19,1.6 P2.6 ; P2.6 57.07,1.6 ; P2.6 55.19,3.48 ; P2.6 57.07,3.48 ; 57.73,1.6 P2.7 ; P2.7 59.61,1.6 ; P2.7 57.73,3.48 ; P2.7 59.61,3.48 ; P31.1 30.29,52.03 ; P31.1 29.06,50.8 ; P31.1 31.52,50.8 ; P31.1 30.29,49.57 ; P13.5 145.29,42.34 ; P13.5 144.09,41.15 ; P13.5 146.48,41.15 ; P13.5 145.29,39.95 ; P8.11 147.83,5.77 ; P8.11 149.02,4.57 ; P8.11 146.63,4.57 ; P8.11 147.83,3.38 ; P5.4 41.91,52.06 ; P5.4 43.17,50.8 ; P5.4 40.65,50.8 ; P5.4 41.91,49.54 ; 12.29,31.56 P28.1 ; P28.1 14.76,31.56 ; P28.1 13.53,30.33 ; P28.1 13.53,32.79 ; 11.11,2.48 P26.1 ; P26.1 14.29,2.48 ; P26.1 12.7,4.06 ; P26.1 12.7,0.89
  L3_SIG w0.381: P14.1 6.21,6.1 ; P14.1 4.83,4.71 ; P14.1 3.44,6.1 ; P14.1 4.83,7.48 ; P8.5 146.48,4.57 ; P8.5 144.09,4.57 ; P8.5 145.29,3.38 ; P8.5 145.29,5.77 ; 12.7,0.89 P26.1 ; P26.1 14.29,2.48 ; P26.1 11.11,2.48 ; P26.1 12.7,4.06 ; 13.53,30.33 P28.1 ; P28.1 13.53,32.79 ; P28.1 12.29,31.56 ; P28.1 14.76,31.56 ; 41.91,49.54 P5.4 ; P5.4 43.17,50.8 ; P5.4 41.91,52.06 ; P5.4 40.65,50.8 ; 2.1,15.85 P24.1 ; P24.1 0.86,17.08 ; P24.1 2.1,18.31 ; P24.1 3.33,17.08 ; 143.7,17.82 P29.1 ; P29.1 143.7,20.28 ; P29.1 144.93,19.05 ; P29.1 142.47,19.05 ; 29.06,50.8 P31.1 ; P31.1 30.29,52.03 ; P31.1 31.52,50.8 ; P31.1 30.29,49.57 ; P2.7 59.61,3.48 ; P2.7 57.73,1.6 ; P2.7 59.61,1.6 ; P2.7 57.73,3.48 ; 147.83,39.95 P13.11 ; P13.11 146.63,41.15 ; P13.11 149.02,41.15 ; P13.11 147.83,42.34 ; P27.1 150.39,34.29 ; P27.1 147.93,34.29 ; P27.1 149.16,35.52 ; P27.1 149.16,33.06 ; P2.6 57.07,1.6 ; P2.6 55.19,1.6 ; P2.6 57.07,3.48 ; P2.6 55.19,3.48 ; P25.1 137.88,42.42 ; P25.1 135.42,42.42 ; P25.1 136.65,41.19 ; P25.1 136.65,43.65 ; 146.63,4.57 P8.11 ; P8.11 147.83,5.77 ; P8.11 149.02,4.57 ; P8.11 147.83,3.38 ; P13.5 145.29,42.34 ; P13.5 144.09,41.15 ; P13.5 146.48,41.15 ; P13.5 145.29,39.95 ; P30.1 136.55,1.91 ; P30.1 135.32,3.14 ; P30.1 134.09,1.91
  L4_GND w0.381: P5.4 43.17,50.8 ; P5.4 40.65,50.8 ; P5.4 41.91,52.06 ; P5.4 41.91,49.54 ; P30.1 136.55,1.91 ; P30.1 134.09,1.91 ; P30.1 135.32,3.14 ; P13.5 145.29,42.34 ; P13.5 146.48,41.15 ; P13.5 144.09,41.15 ; P13.5 145.29,39.95 ; 57.73,3.48 P2.7 ; P2.7 59.61,1.6 ; P2.7 59.61,3.48 ; P2.7 57.73,1.6 ; P2.6 57.07,1.6 ; P2.6 57.07,3.48 ; P2.6 55.19,1.6 ; P2.6 55.19,3.48 ; 136.65,41.19 P25.1 ; P25.1 136.65,43.65 ; P25.1 137.88,42.42 ; P25.1 135.42,42.42 ; 11.11,2.48 P26.1 ; P26.1 14.29,2.48 ; P26.1 12.7,0.89 ; P26.1 12.7,4.06 ; P13.11 149.02,41.15 ; P13.11 146.63,41.15 ; P13.11 147.83,39.95 ; P13.11 147.83,42.34 ; 147.83,3.38 P8.11 ; P8.11 146.63,4.57 ; P8.11 147.83,5.77 ; P8.11 149.02,4.57 ; 149.16,33.06 P27.1 ; P27.1 147.93,34.29 ; P27.1 149.16,35.52 ; P27.1 150.39,34.29 ; 3.44,6.1 P14.1 ; P14.1 4.83,4.71 ; P14.1 6.21,6.1 ; P14.1 4.83,7.48 ; 30.29,49.57 P31.1 ; P31.1 30.29,52.03 ; P31.1 29.06,50.8 ; P31.1 31.52,50.8 ; 0.86,17.08 P24.1 ; P24.1 2.1,18.31 ; P24.1 2.1,15.85 ; P24.1 3.33,17.08 ; P8.5 146.48,4.57 ; P8.5 145.29,5.77 ; P8.5 144.09,4.57 ; P8.5 145.29,3.38 ; 13.53,30.33 P28.1 ; P28.1 12.29,31.56 ; P28.1 13.53,32.79 ; P28.1 14.76,31.56 ; 143.7,17.82 P29.1 ; P29.1 142.47,19.05 ; P29.1 144.93,19.05 ; P29.1 143.7,20.28
  L5_PWR w0.381: 146.63,4.57 P8.11 ; P8.11 149.02,4.57 ; P8.11 147.83,5.77 ; P8.11 147.83,3.38 ; P28.1 13.53,32.79 ; P28.1 13.53,30.33 ; P28.1 12.29,31.56 ; P28.1 14.76,31.56 ; P30.1 136.55,1.91 ; P30.1 134.09,1.91 ; P30.1 135.32,3.14 ; P25.1 137.88,42.42 ; P25.1 136.65,41.19 ; P25.1 136.65,43.65 ; P25.1 135.42,42.42 ; P26.1 14.29,2.48 ; P26.1 12.7,0.89 ; P26.1 11.11,2.48 ; P26.1 12.7,4.06 ; 142.47,19.05 P29.1 ; P29.1 143.7,17.82 ; P29.1 143.7,20.28 ; P29.1 144.93,19.05 ; P27.1 150.39,34.29 ; P27.1 147.93,34.29 ; P27.1 149.16,35.52 ; P27.1 149.16,33.06 ; P14.1 4.83,7.48 ; P14.1 4.83,4.71 ; P14.1 6.21,6.1 ; P14.1 3.44,6.1 ; 145.29,39.95 P13.5 ; P13.5 145.29,42.34 ; P13.5 144.09,41.15 ; P13.5 146.48,41.15 ; P31.1 30.29,52.03 ; P31.1 29.06,50.8 ; P31.1 31.52,50.8 ; P31.1 30.29,49.57 ; P2.7 59.61,1.6 ; P2.7 59.61,3.48 ; P2.7 57.73,1.6 ; P2.7 57.73,3.48 ; 55.19,3.48 P2.6 ; P2.6 57.07,3.48 ; P2.6 55.19,1.6 ; P2.6 57.07,1.6 ; P13.11 149.02,41.15 ; P13.11 147.83,42.34 ; P13.11 146.63,41.15 ; P13.11 147.83,39.95 ; P24.1 2.1,18.31 ; P24.1 0.86,17.08 ; P24.1 3.33,17.08 ; P24.1 2.1,15.85 ; P5.4 43.17,50.8 ; P5.4 40.65,50.8 ; P5.4 41.91,52.06 ; 145.29,3.38 P8.5 ; P8.5 144.09,4.57 ; P8.5 145.29,5.77 ; P8.5 146.48,4.57
  L7_GND w0.381: 11.11,2.48 P26.1 ; P26.1 12.7,4.06 ; P26.1 12.7,0.89 ; P26.1 14.29,2.48 ; P8.11 147.83,5.77 ; P8.11 147.83,3.38 ; P8.11 146.63,4.57 ; P8.11 149.02,4.57 ; P30.1 135.32,3.14 ; P30.1 134.09,1.91 ; P30.1 136.55,1.91 ; P13.11 147.83,42.34 ; P13.11 146.63,41.15 ; P13.11 147.83,39.95 ; P13.11 149.02,41.15 ; P27.1 149.16,35.52 ; P27.1 150.39,34.29 ; P27.1 147.93,34.29 ; P27.1 149.16,33.06 ; 144.09,41.15 P13.5 ; P13.5 145.29,42.34 ; P13.5 145.29,39.95 ; P13.5 146.48,41.15 ; 13.53,30.33 P28.1 ; P28.1 14.76,31.56 ; P28.1 13.53,32.79 ; P28.1 12.29,31.56 ; P2.7 59.61,3.48 ; P2.7 57.73,3.48 ; P2.7 59.61,1.6 ; P2.7 57.73,1.6 ; P5.4 43.17,50.8 ; P5.4 41.91,49.54 ; P5.4 40.65,50.8 ; P5.4 41.91,52.06 ; P29.1 144.93,19.05 ; P29.1 142.47,19.05 ; P29.1 143.7,17.82 ; P29.1 143.7,20.28 ; P31.1 31.52,50.8 ; P31.1 30.29,49.57 ; P31.1 30.29,52.03 ; P31.1 29.06,50.8 ; 4.83,4.71 P14.1 ; P14.1 6.21,6.1 ; P14.1 4.83,7.48 ; P14.1 3.44,6.1 ; P8.5 146.48,4.57 ; P8.5 145.29,5.77 ; P8.5 145.29,3.38 ; P8.5 144.09,4.57 ; P25.1 136.65,43.65 ; P25.1 135.42,42.42 ; P25.1 136.65,41.19 ; P25.1 137.88,42.42 ; 55.19,3.48 P2.6 ; P2.6 55.19,1.6 ; P2.6 57.07,1.6 ; P2.6 57.07,3.48 ; P24.1 3.33,17.08 ; P24.1 2.1,18.31 ; P24.1 0.86,17.08 ; P24.1 2.1,15.85
  L8_SIG w0.381: 147.83,39.95 P13.11 ; P13.11 146.63,41.15 ; P13.11 149.02,41.15 ; P13.11 147.83,42.34 ; P8.11 149.02,4.57 ; P8.11 146.63,4.57 ; P8.11 147.83,5.77 ; P8.11 147.83,3.38 ; P29.1 143.7,20.28 ; P29.1 144.93,19.05 ; P29.1 143.7,17.82 ; P29.1 142.47,19.05 ; P26.1 12.7,4.06 ; P26.1 12.7,0.89 ; P26.1 14.29,2.48 ; P26.1 11.11,2.48 ; 57.73,3.48 P2.7 ; P2.7 57.73,1.6 ; P2.7 59.61,3.48 ; P2.7 59.61,1.6 ; 55.19,1.6 P2.6 ; P2.6 57.07,3.48 ; P2.6 55.19,3.48 ; P2.6 57.07,1.6 ; P27.1 150.39,34.29 ; P27.1 147.93,34.29 ; P27.1 149.16,33.06 ; P27.1 149.16,35.52 ; 2.1,15.85 P24.1 ; P24.1 0.86,17.08 ; P24.1 3.33,17.08 ; P24.1 2.1,18.31 ; P30.1 135.32,3.14 ; P30.1 134.09,1.91 ; P30.1 136.55,1.91 ; 29.06,50.8 P31.1 ; P31.1 30.29,52.03 ; P31.1 30.29,49.57 ; P31.1 31.52,50.8 ; 3.44,6.1 P14.1 ; P14.1 4.83,4.71 ; P14.1 4.83,7.48 ; P14.1 6.21,6.1 ; P5.4 41.91,52.06 ; P5.4 43.17,50.8 ; P5.4 41.91,49.54 ; P5.4 40.65,50.8 ; 144.09,41.15 P13.5 ; P13.5 145.29,42.34 ; P13.5 146.48,41.15 ; P13.5 145.29,39.95 ; P28.1 14.76,31.56 ; P28.1 12.29,31.56 ; P28.1 13.53,32.79 ; P28.1 13.53,30.33 ; 136.65,41.19 P25.1 ; P25.1 135.42,42.42 ; P25.1 136.65,43.65 ; P25.1 137.88,42.42 ; P8.5 146.48,4.57 ; P8.5 144.09,4.57 ; P8.5 145.29,5.77 ; P8.5 145.29,3.38
  L9_GND w0.381: 136.65,41.19 P25.1 ; P25.1 137.88,42.42 ; P25.1 135.42,42.42 ; P25.1 136.65,43.65 ; P28.1 13.53,32.79 ; P28.1 12.29,31.56 ; P28.1 14.76,31.56 ; P28.1 13.53,30.33 ; 57.73,1.6 P2.7 ; P2.7 57.73,3.48 ; P2.7 59.61,3.48 ; P2.7 59.61,1.6 ; P14.1 6.21,6.1 ; P14.1 4.83,7.48 ; P14.1 3.44,6.1 ; P14.1 4.83,4.71 ; 143.7,17.82 P29.1 ; P29.1 142.47,19.05 ; P29.1 144.93,19.05 ; P29.1 143.7,20.28 ; 145.29,3.38 P8.5 ; P8.5 145.29,5.77 ; P8.5 146.48,4.57 ; P8.5 144.09,4.57 ; P26.1 14.29,2.48 ; P26.1 11.11,2.48 ; P26.1 12.7,0.89 ; P26.1 12.7,4.06 ; P24.1 2.1,18.31 ; P24.1 3.33,17.08 ; P24.1 2.1,15.85 ; P24.1 0.86,17.08 ; P30.1 136.55,1.91 ; P30.1 134.09,1.91 ; P30.1 135.32,3.14 ; P8.11 147.83,5.77 ; P8.11 149.02,4.57 ; P8.11 146.63,4.57 ; P8.11 147.83,3.38 ; 147.83,39.95 P13.11 ; P13.11 146.63,41.15 ; P13.11 147.83,42.34 ; P13.11 149.02,41.15 ; 55.19,1.6 P2.6 ; P2.6 57.07,3.48 ; P2.6 55.19,3.48 ; P2.6 57.07,1.6 ; P13.5 145.29,42.34 ; P13.5 146.48,41.15 ; P13.5 144.09,41.15 ; P13.5 145.29,39.95 ; P5.4 43.17,50.8 ; P5.4 41.91,52.06 ; P5.4 40.65,50.8 ; P5.4 41.91,49.54 ; P27.1 150.39,34.29 ; P27.1 149.16,35.52 ; P27.1 149.16,33.06 ; P27.1 147.93,34.29 ; P31.1 31.52,50.8 ; P31.1 29.06,50.8 ; P31.1 30.29,52.03 ; P31.1 30.29,49.57
  BOTTOM w0.127: U7.E5 v1(77.76,28.48) ; U7.C1 v1(79.76,23.72) ; U7.B3 v1(80.76,25.72) ; U6.E5 v1(77.77,37.43)
  BOTTOM w0.254: v1(8.76,27.88) 9.05,28.16 D7.A ; D6.A 9.05,26.32 v1(8.76,26.61)
  BOTTOM w0.381: 12.29,31.56 P28.1 ; P28.1 13.53,32.79 ; P28.1 14.76,31.56 ; P28.1 13.53,30.33 ; v1(59.5,29.34) 59.5,29.33 Y1.2 ; C34.1 29.53,6.7 ; C34.1 28.94,6.15 ; C34.1 30.11,6.15 ; 147.83,3.38 P8.11 ; P8.11 147.83,5.77 ; P8.11 149.02,4.57 ; P8.11 146.63,4.57 ; 77.73,28.1 U7.E5 ; U7.E5 78.14,28.51 ; U7.E5 78.54,28.1 ; 36.36,5.91 C39.2 ; C39.2 36.36,6.92 ; C39.2 36.89,6.41 ; U7.B3 81.14,26.51 ; U7.B3 81.14,25.69 ; U7.B3 81.54,26.1 ; P2.6 57.07,1.6 ; P2.6 55.19,1.6 ; P2.6 55.19,3.48 ; P2.6 57.07,3.48 ; 58.86,43.91 C88.2 58.28,43.36 ; 134.09,1.91 P30.1 ; P30.1 136.55,1.91 ; P30.1 135.32,3.14 ; 36.38,6.97 C38.1 ; C38.1 36.92,7.56 ; C38.1 36.38,8.14 ; 62.03,31.23 C62.2 ; C62.2 62.03,32.44 v1(62.04,32.45) ; C62.2 62.58,31.81 ; U7.C1 80.14,24.51 ; U7.C1 80.54,24.1 ; U7.C1 80.14,23.69 ; U7.C1 79.73,24.1 ; Y1.4 62.47,30.48 ; Y1.4 61.75,31.16 ; Y1.4 62.04,30.77 v1(62.04,31.18) ; P2.7 59.61,3.48 ; P2.7 59.61,1.6 ; P2.7 57.73,3.48 ; P2.7 57.73,1.6 ; 106.16,27.75 C53.2 ; C53.2 107.33,27.75 ; C53.2 106.74,27.2 ; 107.73,25.59 C47.2 ; C47.2 108.24,25.05 ; C47.2 108.74,25.59 ; 104.43,31.18 C60.2 ; C60.2 104.43,32.19 ; C60.2 104.96,31.69 ; 98.73,34.41 C35.2 ; C35.2 99.9,34.41 ; C35.2 v1(99.31,35.05) ; 145.29,39.95 P13.5 ; P13.5 144.09,41.15 ; P13.5 146.48,41.15 ; P13.5 145.29,42.34 ; 28.75,12.96 R4.2 28.13,12.39 ; P8.5 145.29,5.77 ; P8.5 144.09,4.57 ; P8.5 145.29,3.38 ; P8.5 146.48,4.57 ; 2.1,15.85 P24.1 ; P24.1 2.1,18.31 ; P24.1 0.86,17.08 ; P24.1 3.33,17.08 ; 54.79,40.64 C73.2 ; C73.2 55.62,39.66 ; C73.2 55.62,41.62 ; C73.2 56.44,40.64 ; 106.43,25.59 C61.2 ; C61.2 107.44,25.59 ; C61.2 106.93,25.05 ; 12.7,0.89 P26.1 ; P26.1 14.29,2.48 ; P26.1 12.7,4.06 ; P26.1 11.11,2.48 ; C63.2 v1(58.42,31.81) ; P27.1 150.39,34.29 ; P27.1 149.16,33.06 ; P27.1 147.93,34.29 ; P27.1 149.16,35.52 ; 29.06,50.8 P31.1 ; P31.1 31.52,50.8 ; P31.1 30.29,49.57 ; P31.1 30.29,52.03 ; v1(104.9,33.97) C22.2 104.4,33.98 C75.2 104.4,36.17 C26.2 ; C94.2 48.16,36.97 ; C94.2 48.7,36.39 ; C94.2 48.16,35.8 ; 147.83,39.95 P13.11 ; P13.11 146.63,41.15 ; P13.11 147.83,42.34 ; P13.11 149.02,41.15 ; 30.23,6.13 C36.2 ; C36.2 31.24,6.13 ; C36.2 30.73,6.66 ; 99.51,30.96 C50.2 ; C50.2 100.04,31.46 ; C50.2 99.51,31.97 ; C74.2 106.14,24.38 ; C74.2 105.12,24.38 ; C74.2 105.63,23.85 ; 135.42,42.42 P25.1 ; P25.1 136.65,41.19 ; P25.1 137.88,42.42 ; P25.1 136.65,43.65 ; 38.77,40.83 R147.1 ; R147.1 39.97,42.48 ; R147.1 39.97,39.18 ; R147.1 41.18,40.83 ; 106.74,31.2 C45.2 107.33,30.66 ; P29.1 144.93,19.05 ; P29.1 142.47,19.05 ; P29.1 143.7,20.28 ; P29.1 143.7,17.82 ; 55.47,39.05 C72.1 ; C72.1 56.01,38.47 ; C72.1 56.01,39.64 ; 61.61,43.98 C68.2 ; C68.2 62.36,43.26 ; C68.2 62.36,44.7 ; C68.2 63.11,43.98 ; U6.C1 80.55,33.05 ; U6.C1 79.74,33.05 ; U6.C1 80.14,33.46 ; 61.61,43.36 C93.1 61.02,43.91 ; 39.74,34.82 C103.1 ; C103.1 38.78,36.83 ; C103.1 40.69,36.83 ; 4.83,4.71 P14.1 ; P14.1 3.44,6.1 ; P14.1 6.21,6.1 ; P14.1 4.83,7.48 ; 35.97,4.32 C37.1 ; C37.1 37.02,3.06 ; C37.1 37.02,5.58 ; C37.1 38.07,4.32 ; 78.14,37.46 U6.E5 77.74,37.05 ; C65.1 v6(59.94,44.01) ; C26.2 104.96,36.2 ; C26.2 104.42,36.78 ; C26.2 104.42,35.61 ; P5.4 43.17,50.8 ; P5.4 40.65,50.8 ; P5.4 41.91,52.06 ; P5.4 41.91,49.54 ; U6.B3 81.14,35.46 ; U6.B3 81.14,34.65 ; U6.B3 81.55,35.05 ; C24.2 104.45,31.13 ; C24.2 105,30.54 ; C24.2 104.45,29.96 ; C25.2 v1(104.9,32.83)
  BOTTOM w0.508: R4.2 28.14,12.95 v6(29.08,12.95) ; P10.B1 P10.A12 8.74,24.28 8.86,24.16 C120.2 ; P10.A1 P10.B12
  BOTTOM w1.016: R147.1 39.74,40.59 C103.1
  vias: v1(43.15,32.32) v1(43.18,38.32) v1(48.45,27.43) v1(48.45,25.46) v1(50.01,36.7) v1(50.01,36.07) v1(54.01,37.27) v1(54.01,35.5) v1(64.93,34.48) v1(64.96,26.57) v1(64.96,22.89) v1(64.96,20.16) v1(66.17,39.08) v1(70.42,19.43) v1(71.37,21.08) v1(72.52,21.72) v1(75.12,16.16) v1(75.88,35.43) v1(75.88,33.69) v1(75.88,31.59) v1(75.88,29.15) v1(76.45,29.15) v1(76.45,26.48) v1(76.45,24.73) v1(76.64,30.73) v1(76.77,35.21) v1(76.68,29.97) v1(77.03,38.04) v1(77.15,24.48) v1(77.28,26.16) v1(77.47,35.88) v1(77.47,23.75) v1(77.6,33.18) v1(77.76,28.99) v1(78.17,38.04) v1(78.23,31.27) v1(78.49,18.13) v1(78.49,16.16) v1(78.64,26.89) v1(79.31,38.04) v1(79.63,36.51) v1(79.63,24.45) v1(79.82,22.35) v1(80.07,28.7) v1(80.14,19.02) v1(80.33,38.86) v1(80.45,22.92) v1(80.58,23.75) v1(80.68,24.64) v1(81.53,38.86) v1(81.52,34.6) v1(81.57,32.64) v1(81.63,23.53) v1(81.91,35.56) v1(82.61,22.92) v1(82.87,38.86) v1(82.8,30.04) v1(83.03,27.81) v1(83.23,24.72) v1(83.23,23.72) v1(83.44,33.94) v1(83.44,32.83) v1(83.57,35.85) v1(83.57,25.46) v1(83.85,37.08) v1(84.42,32.83) v1(84.39,30.04) v1(84.39,28.99) v1(84.77,25.46) v1(85.38,33.85) v1(85.85,25.46) v1(87.12,28.89) v1(87.5,28.13) v1(87.5,26.8) v1(88.01,30.16) v1(88.52,28.13) v1(88.52,26.8) v1(88.8,31.05) v1(89.41,32.29) v1(89.5,35.85) v1(91.22,30.16) v1(92.14,30.16) v1(92.74,33.02) v1(99.28,22.67) v1(99.95,32.39) v1(99.98,31.94) v1(104.97,36.2) v1(104.97,35.62) v1(106.36,24.7) v1(106.74,32.16) v1(106.74,31.72) v1(107,24.73) v1(107.44,27.97) v1(108.24,24.73) v1(108.36,30.48) v1(108.87,30.48) v1(108.97,27.97) v1(109.32,32.16) v1(116.2,17.59) v1(116.84,44.26) v1(116.9,47.43) v1(129.03,11.24) v1(132.33,11.24) v1(137.92,28.83) v1(137.92,24.57) v1(143.76,21.72) v1(148.78,27.69) v1(148.78,25.72) v2(95.44,28.04) v2(96.62,28.04) v2(97.6,28.04) v2(98.87,23.81) v2(99.19,23.81) v2(101.65,30.15) v2(101.79,23.81) v2(102,30.15) v2(101.98,22.67) v2(101.98,22.35) v2(102.11,23.81) v2(102.27,22.67) v2(102.27,22.35) v2(103.38,30.99) v2(103.63,31.05) v2(103.7,30.16) v2(103.85,31.4) v2(103.85,31.18) v2(103.95,30.26) v2(104.04,31.59) v2(104.08,31.37) v2(104.17,30.35) v2(104.24,31.78) v2(104.27,31.56) v2(104.36,30.26) v2(104.43,31.97) v2(104.46,31.75) v2(104.39,30.48) v2(104.62,32.16) v2(104.65,31.94) v2(104.58,30.64) v2(104.62,30.42) v2(104.77,30.8) v2(104.81,32.35) v2(104.84,32.13) v2(104.81,30.58) v2(104.97,30.99) v2(105,32.54) v2(105.03,32.32) v2(105,30.77) v2(105.16,31.18) v2(105.19,32.73) v2(105.22,32.51) v2(105.19,30.96) v2(105.35,31.37) v2(105.38,32.92) v2(105.41,32.7) v2(105.38,31.15) v2(105.57,33.12) v2(105.54,31.56) v2(105.57,31.34) v2(105.6,32.89) v2(105.76,33.31) v2(105.73,31.75) v2(105.76,31.53) v2(105.79,33.08) v2(105.95,33.5) v2(105.92,31.94) v2(105.95,31.72) v2(105.98,33.27) v2(106.14,33.69) v2(106.17,33.46) v2(106.11,32.13) v2(106.14,31.91) v2(106.11,29.53) v2(106.11,29.08) v2(106.33,33.88) v2(106.36,33.66) v2(106.3,32.32) v2(106.33,32.1) v2(106.52,34.07) v2(106.55,33.85) v2(106.49,32.51) v2(106.52,32.29) v2(106.49,27.97) v2(106.71,34.26) v2(106.74,34.04) v2(106.68,32.7) v2(106.71,32.48) v2(106.87,32.89) v2(106.9,34.45) v2(106.93,34.23) v2(106.9,32.67) v2(107.06,33.08) v2(107.09,34.64) v2(107.12,34.42) v2(107.09,32.86) v2(107.12,29.53) v2(107.12,29.08) v2(107.25,33.27) v2(107.28,34.83) v2(107.31,34.61) v2(107.28,33.05) v2(107.47,35.02) v2(107.44,33.46) v2(107.47,33.24) v2(107.51,34.8) v2(107.66,35.21) v2(107.63,33.66) v2(107.66,33.43) v2(107.7,34.99) v2(107.85,35.4) v2(107.82,33.85) v2(107.85,33.62) v2(107.89,35.18) v2(107.95,27.97) v2(108.05,35.59) v2(108.01,34.04) v2(108.05,33.81) v2(108.08,35.37) v2(108.14,29.53) v2(108.14,29.08) v2(108.24,35.78) v2(108.27,35.56) v2(108.2,34.23) v2(108.24,34) v2(108.43,35.97) v2(108.46,35.75) v2(108.39,34.42) v2(108.43,34.19) v2(108.39,27.97) v2(108.62,36.16) v2(108.65,35.94) v2(108.58,34.61) v2(108.62,34.39) v2(108.78,34.8) v2(108.81,36.35) v2(108.84,36.13) v2(108.81,34.58) v2(108.97,34.99) v2(109,36.54) v2(109.03,36.32) v2(109,34.77) v2(109.16,35.18) v2(109.19,36.73) v2(109.22,36.51) v2(109.19,34.96) v2(109.35,35.37) v2(109.38,36.93) v2(109.41,36.7) v2(109.38,35.15) v2(109.57,37.12) v2(109.54,35.56) v2(109.57,35.34) v2(109.6,36.89) v2(109.76,37.31) v2(109.73,35.75) v2(109.76,35.53) v2(109.79,37.08) v2(109.95,37.5) v2(109.92,35.94) v2(109.95,35.72) v2(109.98,37.27) v2(110.14,37.69) v2(110.17,37.47) v2(110.11,36.13) v2(110.14,35.91) v2(110.33,37.88) v2(110.36,37.66) v2(110.3,36.32) v2(110.33,36.1) v2(110.52,38.07) v2(110.55,37.85) v2(110.49,36.51) v2(110.52,36.29) v2(110.71,38.26) v2(110.74,38.04) v2(110.68,36.7) v2(110.71,36.48) v2(110.87,36.89) v2(110.9,38.45) v2(110.93,38.23) v2(110.9,36.67) v2(111.06,37.08) v2(111.09,38.64) v2(111.12,38.42) v2(111.09,36.86) v2(111.25,37.27) v2(111.28,38.83) v2(111.32,38.61) v2(111.28,37.05) v2(111.47,39.02) v2(111.44,37.47) v2(111.47,37.24) v2(111.51,38.8) v2(111.66,39.21) v2(111.63,37.66) v2(111.66,37.43) v2(111.73,52.61) v2(111.73,52.36) v2(111.73,52.1) v2(111.73,51.85) v2(111.73,51.59) v2(111.73,51.34) v2(111.73,51.09) v2(111.73,50.83) v2(111.73,50.58) v2(111.73,50.32) v2(111.73,50.07) v2(111.73,49.82) v2(111.73,49.56) v2(111.73,49.31) v2(111.73,49.05) v2(111.7,38.99) v2(111.79,48.77) v2(111.86,39.4) v2(111.82,37.85) v2(111.86,37.62) v2(111.92,52.74) v2(111.92,52.48) v2(111.92,52.23) v2(111.92,51.97) v2(111.92,51.72) v2(111.92,51.47) v2(111.92,51.21) v2(111.92,50.96) v2(111.92,50.7) v2(111.92,50.45) v2(111.92,50.2) v2(111.92,49.94) v2(111.92,49.69) v2(111.92,49.43) v2(111.92,49.18) v2(111.95,48.96) v2(111.89,39.18) v2(112.05,48.7) v2(112.05,39.59) v2(112.01,38.04) v2(112.05,37.81) v2(112.17,48.89) v2(112.08,39.37) v2(112.24,39.78) v2(112.27,39.56) v2(112.2,38.23) v2(112.24,38) v2(112.3,48.7) v2(112.43,48.89) v2(112.43,39.97) v2(112.46,39.75) v2(112.39,38.42) v2(112.43,38.2) v2(112.55,48.7) v2(112.62,40.16) v2(112.65,39.94) v2(112.59,38.61) v2(112.62,38.39) v2(112.68,48.89) v2(112.81,48.7) v2(112.81,40.35) v2(112.84,40.13) v2(112.78,38.8) v2(112.81,38.58) v2(112.93,48.89) v2(112.97,38.99) v2(113.06,48.7) v2(113,40.54) v2(113.03,40.32) v2(113,38.77) v2(113.16,39.18) v2(113.19,48.89) v2(113.19,40.74) v2(113.22,40.51) v2(113.19,38.96) v2(113.32,48.7) v2(113.35,39.37) v2(113.44,48.89) v2(113.38,40.93) v2(113.41,40.7) v2(113.38,39.15) v2(113.57,48.7) v2(113.57,41.12) v2(113.54,39.56) v2(113.57,39.34) v2(113.6,40.89) v2(113.7,48.89) v2(113.76,41.31) v2(113.73,39.75) v2(113.76,39.53) v2(113.82,48.7) v2(113.79,41.08) v2(113.95,41.5) v2(113.92,39.94) v2(113.95,39.72) v2(113.98,48.89) v2(113.98,41.28) v2(114.11,48.7) v2(114.14,41.69) v2(114.17,41.47) v2(114.11,40.13) v2(114.14,39.91) v2(114.24,48.89) v2(114.27,41.91) v2(114.36,41.66) v2(114.3,40.32) v2(114.33,40.1) v2(114.43,48.64) v2(114.46,42.13) v2(114.49,48.89) v2(114.49,48.39) v2(114.49,48.16) v2(114.49,47.94) v2(114.49,47.69) v2(114.49,47.43) v2(114.49,47.18) v2(114.49,46.93) v2(114.49,46.67) v2(114.49,46.42) v2(114.49,46.16) v2(114.49,45.91) v2(114.49,45.66) v2(114.49,45.4) v2(114.49,45.15) v2(114.52,44.93) v2(114.55,44.7) v2(114.55,44.48) v2(114.55,42.42) v2(114.52,41.85) v2(114.49,40.51) v2(114.52,40.29) v2(114.59,44.26) v2(114.59,44.01) v2(114.59,43.72) v2(114.62,43.4) v2(114.62,43.15) v2(114.62,42.89) v2(114.62,42.64) v2(114.68,48.77) v2(114.68,48.51) v2(114.68,48.26) v2(114.68,48.04) v2(114.68,47.82) v2(114.68,47.56) v2(114.68,47.31) v2(114.68,47.05) v2(114.68,46.8) v2(114.68,46.55) v2(114.68,46.29) v2(114.68,46.04) v2(114.68,45.78) v2(114.68,45.53) v2(114.68,45.28) v2(114.71,45.05) v2(114.68,42.07) v2(114.68,40.7) v2(114.71,40.48) v2(114.87,48.89) v2(114.87,48.64) v2(114.87,48.39) v2(114.87,48.13) v2(114.84,44.86) v2(114.78,44.64) v2(114.78,44.42) v2(114.78,44.13) v2(114.78,43.88) v2(114.81,43.56) v2(114.81,43.28) v2(114.81,43.02) v2(114.81,42.77) v2(114.81,42.51) v2(114.78,42.29) v2(114.87,40.89) v2(114.9,40.67) v2(115.06,41.08) v2(115.09,40.86) v2(115.22,41.28) v2(115.28,41.05) v2(115.47,41.62) v2(115.38,41.43) v2(115.47,41.24) v2(115.54,41.85) v2(115.67,42.29) v2(115.6,42.07) v2(115.63,41.4) v2(115.76,48.89) v2(115.76,48.64) v2(115.76,48.39) v2(115.76,48.13) v2(115.7,43.53) v2(115.7,43.28) v2(115.7,43.02) v2(115.7,42.77) v2(115.7,42.51) v2(115.76,41.91) v2(115.7,41.62) v2(115.82,42.13) v2(115.92,48.77) v2(115.92,48.51) v2(115.92,48.26) v2(115.92,46.8) v2(115.92,46.55) v2(115.92,46.29) v2(115.92,46.04) v2(115.92,45.78) v2(115.92,45.53) v2(115.92,45.28) v2(115.92,45.02) v2(115.92,44.77) v2(115.89,43.66) v2(115.89,43.4) v2(115.89,43.15) v2(115.89,42.89) v2(115.89,42.64) v2(115.89,42.39) v2(116.11,48.89) v2(116.11,48.64) v2(116.11,48.39) v2(116.11,48.13) v2(116.11,46.67) v2(116.11,46.42) v2(116.11,46.16) v2(116.11,45.91) v2(116.11,45.66) v2(116.11,45.4) v2(116.11,45.15) v2(116.11,44.89) v2(116.3,48.77) v2(116.43,52.74) v2(116.43,52.48) v2(116.43,52.23) v2(116.43,51.97) v2(116.43,51.72) v2(116.43,51.47) v2(116.43,51.21) v2(116.43,50.96) v2(116.43,50.7) v2(116.43,50.45) v2(116.43,50.2) v2(116.43,49.94) v2(116.43,49.69) v2(116.43,49.43) v2(116.43,49.18) v2(116.4,48.96) v2(116.55,48.8) v2(116.62,52.61) v2(116.62,52.36) v2(116.62,52.1) v2(116.62,51.85) v2(116.62,51.59) v2(116.62,51.34) v2(116.62,51.09) v2(116.62,50.83) v2(116.62,50.58) v2(116.62,50.32) v2(116.62,50.07) v2(116.62,49.82) v2(116.62,49.56) v2(116.62,49.31) v2(116.62,49.05) v6(0.76,34.04) v6(0.76,33.02) v6(0.76,30.48) v6(0.76,27.94) v6(0.76,25.4) v6(0.76,22.86) v6(0.76,20.32) v6(0.76,17.78) v6(0.76,15.24) v6(0.76,12.7) v6(0.76,10.16) v6(0.76,7.62) v6(0.76,5.08) v6(0.76,2.79) v6(2.54,20.32) v6(2.54,15.24) v6(2.54,12.7) v6(2.54,10.16) v6(2.54,7.62) v6(2.54,5.08) v6(2.79,34.04) v6(2.79,0.76) v6(5.08,17.78) v6(5.08,15.24) v6(5.08,12.7) v6(5.08,2.54) v6(5.08,0.76) v6(7.62,17.78) v6(7.62,15.24) v6(7.62,12.7) v6(7.62,7.62) v6(7.62,5.08) v6(7.62,2.54) v6(7.62,0.76) v6(8.83,18.54) v6(8.83,17.78) v6(10.16,7.62) v6(10.16,5.08) v6(10.16,2.54) v6(10.16,0.76) v6(11.81,31.56) v6(12.57,22.1) v6(12.57,21.4) v6(12.57,20.7) v6(12.57,20) v6(12.7,7.62) v6(12.7,5.08) v6(12.7,0.76) v6(13.34,25.08) v6(14.29,22.1) v6(15.05,22.1) v6(15.24,7.62) v6(15.24,5.08) v6(15.24,2.54) v6(15.24,0.76) v6(15.81,22.1) v6(16.26,30.23) v6(16.26,27.69) v6(16.57,22.1) v6(17.78,7.62) v6(17.78,5.08) v6(17.78,2.54) v6(17.78,0.76) v6(18.8,27.69) v6(20.32,2.54) v6(20.32,0.76) v6(20.51,22.1) v6(21.27,22.1) v6(21.34,27.69) v6(22.03,22.1) v6(22.73,7.18) v6(22.73,5.59) v6(22.8,22.1) v6(22.86,2.54) v6(22.86,0.76) v6(23.88,27.69) v6(24.13,5.59) v6(24.83,16.64) v6(25.27,22.03) v6(25.27,21.21) v6(25.27,20.45) v6(25.4,2.54) v6(25.4,0.76) v6(26.1,22.03) v6(26.1,21.21) v6(26.1,20.45) v6(26.42,27.69) v6(27.3,16.64) v6(27.94,0.76) v6(28.96,27.69) v6(29.08,13.84) v6(29.84,14.73) v6(29.84,13.84) v6(29.84,6.95) v6(30.23,46.74) v6(30.48,52.58) v6(30.51,6.95) v6(30.48,0.76) v6(31.5,45.47) v6(31.5,27.69) v6(33.02,52.58) v6(33.02,0.76) v6(34.04,45.47) v6(34.04,27.69) v6(35.56,52.58) v6(35.56,0.76) v6(35.75,24.07) v6(35.75,23.37) v6(35.75,22.67) v6(36.39,24.07) v6(36.39,23.37) v6(36.39,22.67) v6(36.58,45.47) v6(36.58,27.69) v6(37.15,8.06) v6(37.15,7.37) v6(37.15,6.67) v6(37.97,21.27) v6(37.91,7.37) v6(37.91,6.67) v6(38.1,52.58) v6(38.1,0.76) v6(38.61,21.27) v6(38.67,7.37) v6(38.67,6.67) v6(38.89,43.56) v6(38.89,42.86) v6(39.12,27.69) v6(39.12,22.61) v6(39.24,21.27) v6(39.37,7.37) v6(39.37,6.67) v6(39.37,5.97) v6(39.37,5.27) v6(39.37,4.57) v6(39.37,3.87) v6(39.59,43.56) v6(39.59,42.86) v6(40.29,43.56) v6(40.29,42.86) v6(40.64,52.58) v6(40.64,0.76) v6(41.66,42.93) v6(41.66,40.39) v6(41.66,27.69) v6(41.66,25.15) v6(41.66,22.61) v6(43.18,52.58) v6(43.18,0.76) v6(44.2,40.39) v6(45.47,22.61) v6(45.72,52.58) v6(45.72,0.76) v6(46.42,14.92) v6(46.42,13.91) v6(46.8,14.41) v6(47.18,14.92) v6(47.18,13.91) v6(47.56,14.41) v6(47.62,5.84) v6(47.94,14.92) v6(47.94,13.91) v6(48.01,40.39) v6(48.01,22.61) v6(48.26,52.58) v6(48.26,0.76) v6(48.32,14.41) v6(48.7,14.92) v6(48.7,13.91) v6(50.55,40.39) v6(50.55,31.5) v6(50.55,28.96) v6(50.55,26.42) v6(50.8,52.58) v6(50.8,0.76) v6(50.93,16.38) v6(50.93,15.75) v6(51.56,16.38) v6(51.56,15.75) v6(52.2,16.38) v6(52.2,15.75) v6(53.09,31.5) v6(53.09,28.96) v6(53.09,26.42) v6(53.09,22.61) v6(53.34,52.58) v6(53.34,0.76) v6(54.61,40.64) v6(54.86,18.1) v6(54.8,10.29) v6(54.8,9.53) v6(54.8,8.7) v6(54.99,22.67) v6(55.31,39.05) v6(55.31,6.54) v6(55.31,5.84) v6(55.56,8.7) v6(55.63,31.5) v6(55.63,28.96) v6(55.63,26.42) v6(55.88,52.58) v6(55.88,0.76) v6(56.9,22.61) v6(57.09,14.92) v6(57.09,13.91) v6(57.79,14.92) v6(57.79,13.91) v6(58.17,28.96) v6(58.17,26.42) v6(58.42,52.58) v6(58.42,0.76) v6(58.48,20.45) v6(58.55,14.92) v6(58.55,13.91) v6(58.86,44.7) v6(58.86,44.01) v6(59.25,14.92) v6(59.25,13.91) v6(59.44,22.61) v6(59.94,44.7) v6(60.01,9.14) v6(60.64,38.8) v6(60.64,36) v6(60.71,26.42) v6(60.96,52.58) v6(60.96,0.76) v6(61.02,44.01) v6(61.53,38.8) v6(61.53,37.91) v6(61.53,36.89) v6(61.53,36) v6(61.98,22.61) v6(61.98,18.1) v6(62.55,38.8) v6(62.55,37.91) v6(62.55,36.89) v6(62.55,36) v6(62.93,14.03) v6(63.25,11.18) v6(63.44,37.91) v6(63.44,36) v6(63.5,52.58) v6(63.5,0.76) v6(65.21,6.92) v6(65.21,6.22) v6(65.79,11.18) v6(66.04,52.58) v6(65.98,14.8) v6(65.98,14.03) v6(66.04,0.76) v6(66.61,9.59) v6(67.37,9.59) v6(68.33,13.72) v6(68.33,11.18) v6(68.33,7.37) v6(68.58,52.58) v6(68.58,0.76) v6(71.12,52.58) v6(71.12,0.76) v6(73.66,52.58) v6(73.66,0.76) v6(76.2,52.58) v6(76.2,0.76) v6(78.74,52.58) v6(78.74,0.76) v6(81.28,52.58) v6(81.28,0.76) v6(83.82,52.58) v6(83.82,0.76) v6(86.36,52.58) v6(86.36,0.76) v6(88.9,52.58) v6(88.9,0.76) v6(91.44,52.58) v6(91.44,0.76) v6(93.98,52.58) v6(93.98,0.76) v6(96.52,52.58) v6(96.52,0.76) v6(99.06,52.58) v6(99.06,0.76) v6(100.58,15.18) v6(101.6,52.58) v6(101.6,0.76) v6(104.14,52.58) v6(104.14,48.26) v6(104.14,0.76) v6(105.85,15.46) v6(105.85,14.57) v6(106.68,52.58) v6(106.68,50.8) v6(106.68,48.26) v6(106.68,0.76) v6(106.81,15.46) v6(106.81,14.57) v6(107.76,15.46) v6(107.76,14.57) v6(109.22,52.58) v6(109.22,50.8) v6(109.22,48.26) v6(109.22,45.72) v6(109.22,0.76) v6(110.3,15.43) v6(111,15.43) v6(111.76,45.72) v6(111.76,43.18) v6(111.76,40.64) v6(111.76,0.76) v6(114.3,38.1) v6(114.3,35.56) v6(114.3,0.76) v6(116.84,43.18) v6(116.84,40.64) v6(116.84,38.1) v6(116.84,0.76) v6(119.38,52.58) v6(119.38,50.8) v6(119.38,48.26) v6(119.38,45.72) v6(119.38,43.18) v6(119.38,40.64) v6(119.38,38.1) v6(119.38,0.76) v6(121.92,52.58) v6(121.92,50.8) v6(121.92,48.26) v6(121.92,45.72) v6(121.92,43.18) v6(121.92,40.64) v6(121.92,38.1) v6(121.92,0.76) v6(124.46,52.58) v6(124.46,50.8) v6(124.46,48.26) v6(124.46,45.72) v6(124.46,43.18) v6(124.46,0.76) v6(127,52.58) v6(127,50.8) v6(127,48.26) v6(127,45.72) v6(127,0.76) v6(129.54,52.58) v6(129.54,50.8) v6(129.54,48.26) v6(132.08,52.58) v6(132.08,50.8) v6(132.08,48.26) v6(132.08,0.76) v6(134.62,52.58) v6(134.62,50.8) v6(134.62,48.26) v6(137.16,0.76) v6(139.7,52.58) v6(139.7,0.76) v6(141.67,29.4) v6(141.67,28.38) v6(141.67,24.96) v6(141.67,23.94) v6(142.24,52.58) v6(142.24,0.76) v6(142.81,29.4) v6(142.81,23.94) v6(143.95,29.4) v6(143.95,28.45) v6(143.95,24.96) v6(143.95,23.94) v6(145.16,29.4) v6(145.1,23.94) v6(146.3,29.4) v6(146.3,28.45) v6(146.3,27.3) v6(146.3,26.1) v6(146.3,24.96) v6(146.3,23.94) v6(149.86,52.58) v6(149.86,50.8) v6(149.86,48.26) v6(149.86,45.72) v6(149.86,43.18) v6(149.86,40.64) v6(149.86,38.1) v6(149.86,35.56) v6(149.86,33.02) v6(149.86,30.48) v6(149.86,27.94) v6(149.86,25.4) v6(149.86,22.86) v6(149.86,15.24) v6(149.86,12.7) v6(149.86,10.16) v6(149.86,7.62) v6(149.86,5.08) v6(149.86,2.54) v6(149.86,0.76) v6(151.64,52.58) v6(151.64,50.8) v6(151.64,48.26) v6(151.64,45.72) v6(151.64,43.18) v6(151.64,40.64) v6(151.64,38.1) v6(151.64,35.56) v6(151.64,33.02) v6(151.64,30.48) v6(151.64,27.94) v6(151.64,25.4) v6(151.64,22.86) v6(151.64,20.32) v6(151.64,17.78) v6(151.64,15.24) v6(151.64,12.7) v6(151.64,10.16) v6(151.64,7.62) v6(151.64,5.08) v6(151.64,2.54) v6(151.64,0.76)
